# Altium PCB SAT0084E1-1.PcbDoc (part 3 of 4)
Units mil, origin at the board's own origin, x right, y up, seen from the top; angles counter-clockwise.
Board outline 7055 x 5555 mil, 6 copper layers (Top Layer, MidLayer1-GND, MidLayer2-HiSp, MidLayer3-GND, MidLayer4, Bottom Layer), stack 57.4 mil thick; 379 components, 207 nets, 1026 pads, 1546 vias.
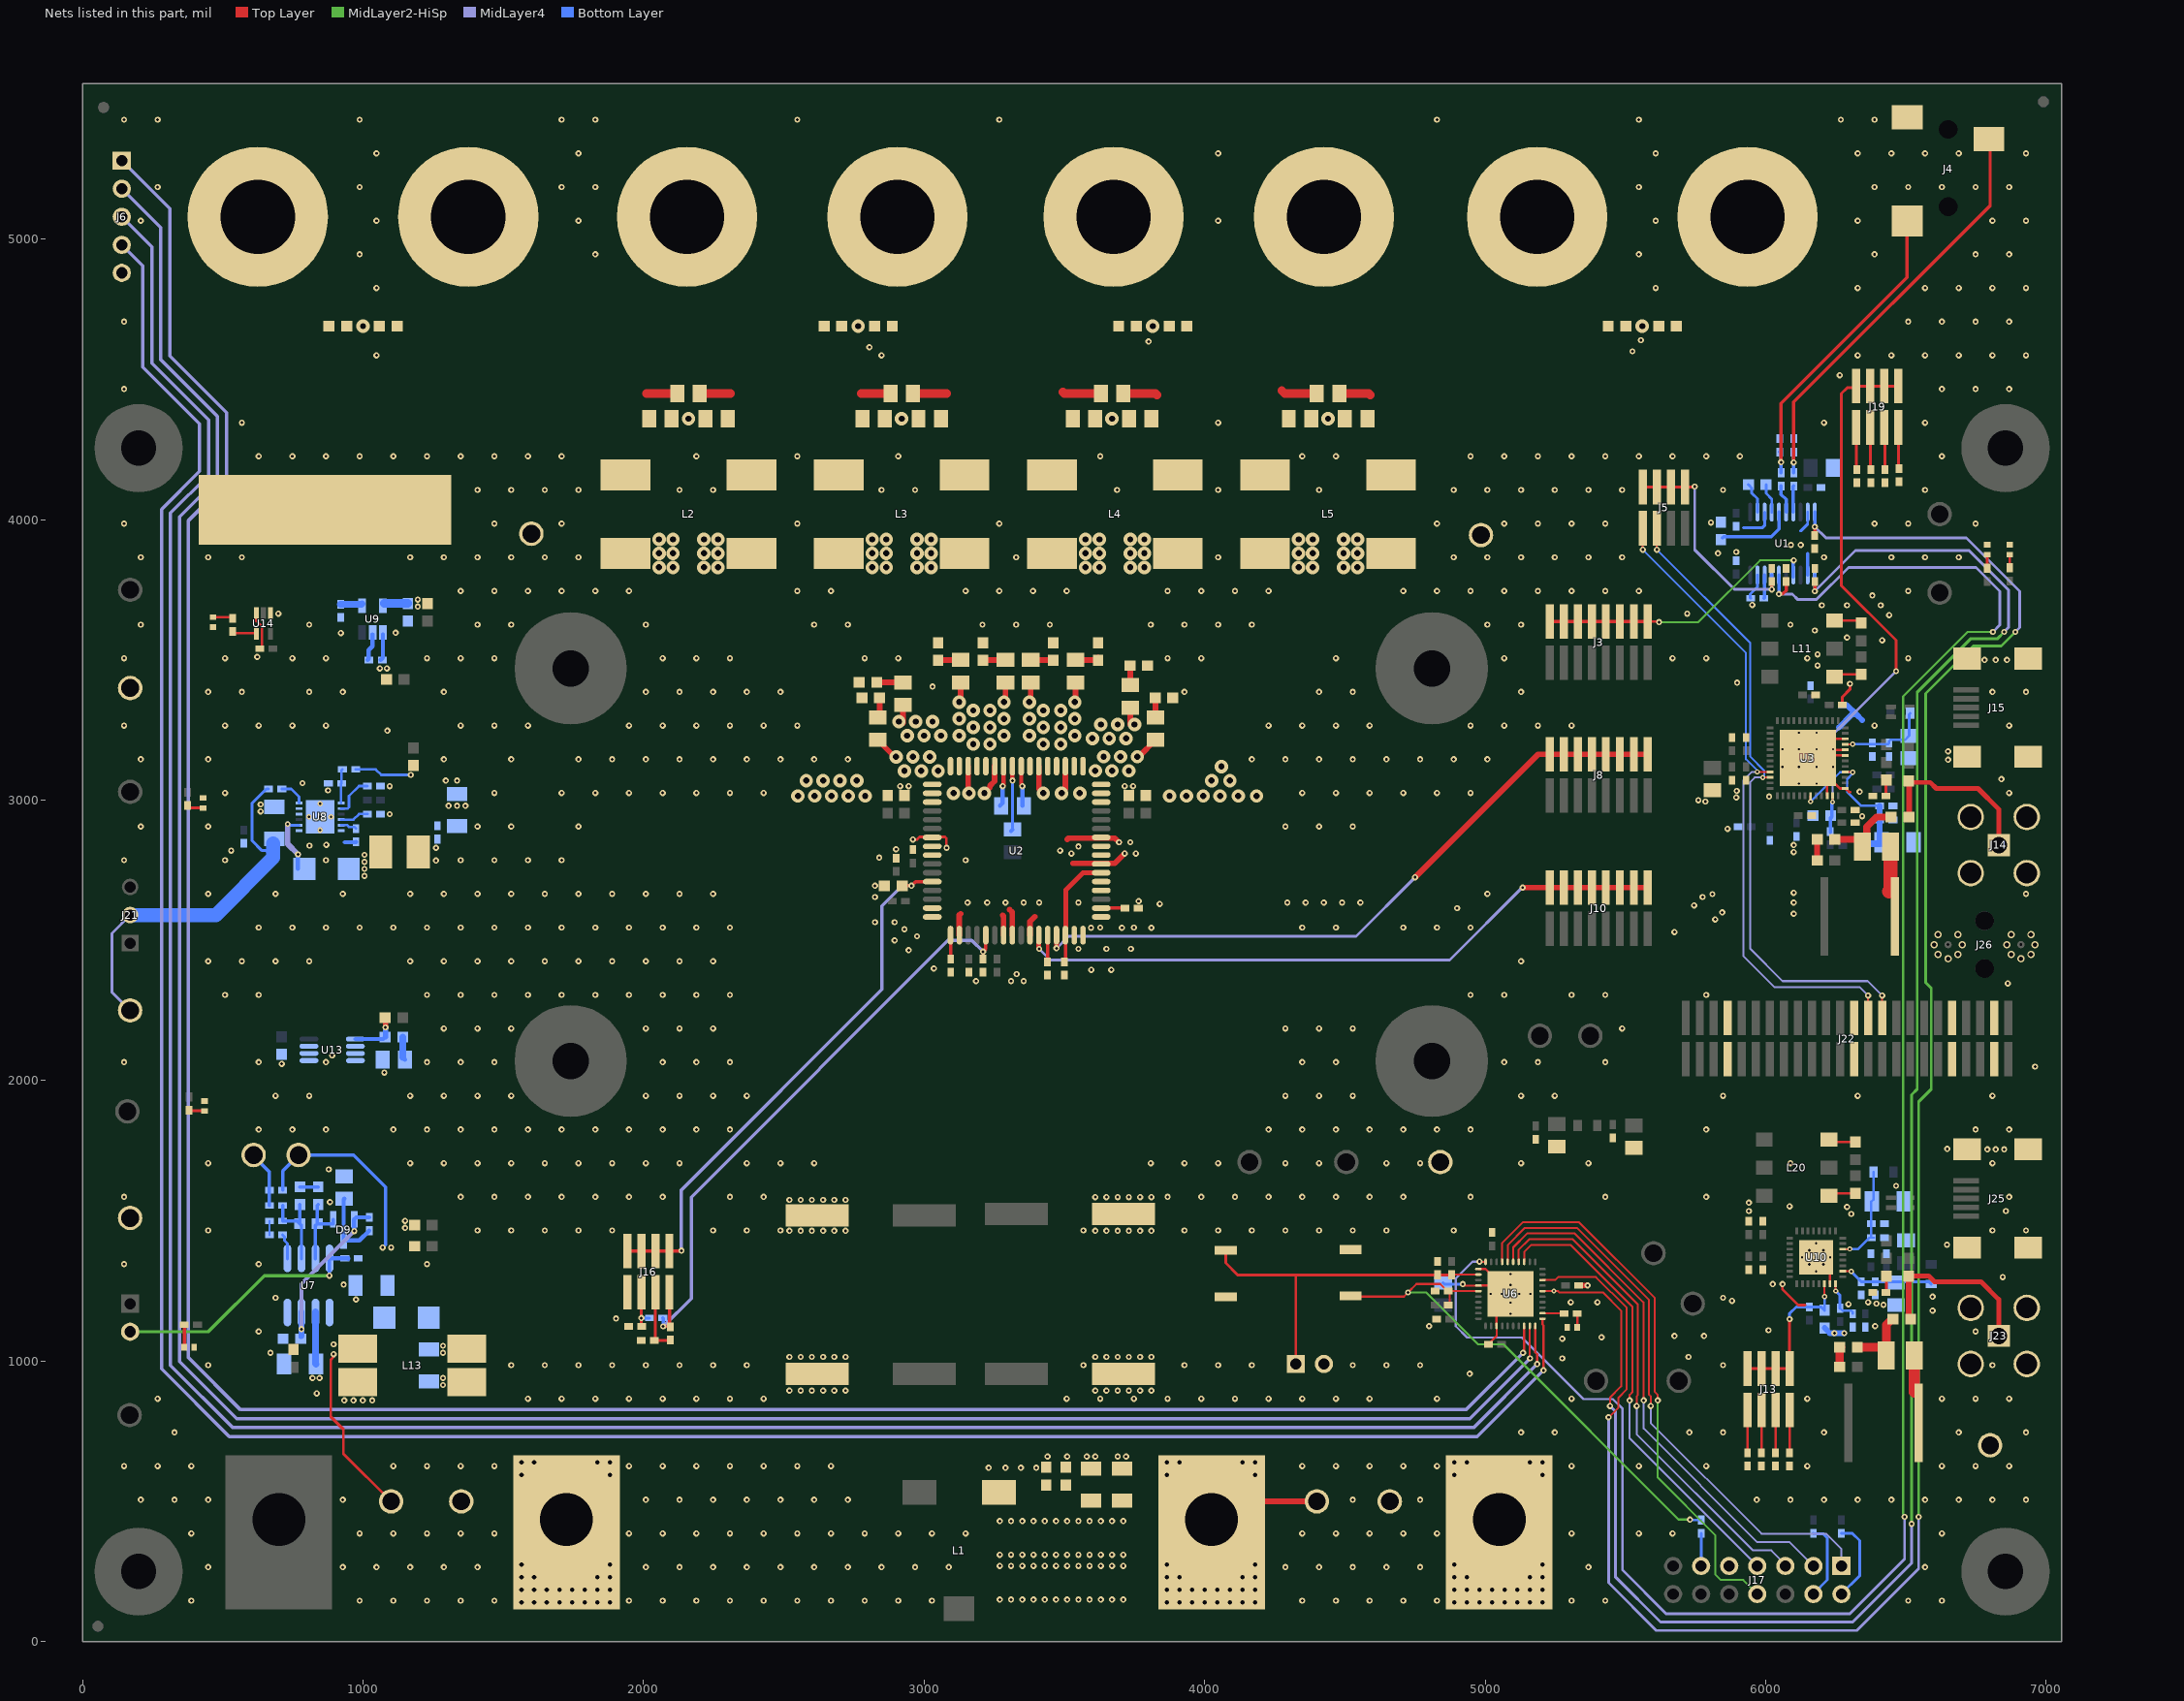
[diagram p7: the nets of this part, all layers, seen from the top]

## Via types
v1: diameter 22, hole 10, Top Layer to Bottom Layer, tented both sides, 1179 vias
v2: diameter 48, hole 22, Top Layer to Bottom Layer, tented both sides, 128 vias
v3: diameter 32, hole 16, Top Layer to Bottom Layer, tented both sides, 112 vias
v4: diameter 18, hole 8, Top Layer to Bottom Layer, tented both sides, 80 vias
v5: diameter 19.68, hole 7.87, Top Layer to Bottom Layer, tented both sides, 30 vias
v6: diameter 26, hole 16, Top Layer to Bottom Layer, 12 vias
v7: diameter 36, hole 16, Top Layer to Bottom Layer, tented both sides, 2 vias
v8: diameter 26, hole 10, Top Layer to Bottom Layer, tented both sides, 1 vias
v9: diameter 20, hole 8, Top Layer to Bottom Layer, tented both sides, 1 vias
v10: diameter 30, hole 12, Top Layer to Bottom Layer, tented both sides, 1 vias

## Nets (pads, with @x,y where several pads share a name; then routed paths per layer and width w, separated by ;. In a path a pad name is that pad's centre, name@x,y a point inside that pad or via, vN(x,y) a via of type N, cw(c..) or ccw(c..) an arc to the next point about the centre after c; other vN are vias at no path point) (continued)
GND: C1.2 C2.2 C3.2 C4.2 C5.2 C6.2 C7.2 C8.2 C9.2 C10.2 C11.2 C12.2 C13.2 C14.2 C15.2 C16.2 C17.2 C18.2 C19.1 C20.2 C21.2 C23.2 C24.2 C25.2 C27.1 C28.2 C29.2 C32.1 C33.1 C34.1 C35.2 C36.1 C37.2 C38.2 C40.1 C41.1 C42.1 C43.1 C44.1 C45.2 C46.2 C48.1 C49.1 C50.1 C51.1 C52.2 C53.2 C55.1 C56.1 C57.1 C58.2 C59.2 C60.2 C61.2 C62.2 C63.2 C64.2 C65.2 C66.2 C67.2 C68.2 C69.2 C70.2 C71.2 C72.2 C73.2 C74.2 C75.2 C76.2 C77.2 C78.2 C87.2 C88.2 C89.2 C91.2 C92.2 C95.2 C96.1 C98.2 C99.2 C100.2 C101.2 C102.2 C103.2 C104.2 C105.2 C106.2 C107.2 C108.2 C109.2 C110.2 C111.2 C112.2 C113.2 C114.2 C115.2 C116.2 C117.2 C118.2 C119.2 C120.2 C127.2 C128.2 C129.2 C130.2 C131.2 C132.2 D1.2 D2.2 D4.2 D6.2 D7.2 D8.2 D10.2 J2.1 J4.1 J6.5 J14.MH1 J14.MH2 J14.MH3 J14.MH4 J15.6 J15.7 J15.8 J15.9 J16.1 J17.9 J20.1 J22.7 J22.8 J22.25 J22.26 J22.39 J22.40 J22.45 J22.46 J23.MH1 J23.MH2 J23.MH3 J23.MH4 J25.6 J25.7 J25.8 J25.9 J26.1A J26.2A J27.2 L13.2 Logo1.0 R1.1 R2.1 R4.1 R5.1 R6.1 R9.2 R10.2 R19.2 R20.2 R25.2 R38.1 R39.1 R40.1 R48.1 R52.1 R53.1 R54.2 R57.1 R63.1 R74.2 R90.1 R91.1 R94.1 R96.1 R98.2 R100.2 R103.1 R104.1 R105.1 R106.1 R107.1 S1.2 S5.1 TP2.1 TP3.1 TP4.1 TP9.1 TP14.1 TP17.1 TP41.1 TP48.1 U1.3 U1.9 U1.12 U1.19 U2.2 U2.7 U2.8 U2.10 U2.15 U2.16 U2.17 U2.20 U2.21 U2.23 U2.24 U2.25 U2.26 U2.30 U2.31 U2.32 U2.35 U2.38 U2.39 U2.43 U2.46 U2.49 U2.50 U2.51 U2.55 U2.56 U2.57 U2.63 U2.64 U3.34 U3.37 U3.43 U3.44 U3.46 U3.49 U6.1 U6.4 U6.13 U6.41 U7.4 U8.4 U8.5 U8.13 U9.2 U10.7 U10.33 U13.2 U13.3 U13.4 U13.5 U13.6 U13.7 U14.1 U14.3 | length 3797.5
  Top Layer w7: v1(4920,1275) 4925.47,1269.53 U6.4@4975.83,1269.53 ; C128.2@5011.38,1060 5040.79,1089.41 U6.13@5040.79,1125.83
  Top Layer w8: U6.4@4975.83,1269.53 U6.41@5060.47,1269.53 ; U6.1@4975.83,1328.58 5001.42,1328.58 U6.41@5060.47,1269.53 ; U6.13@5040.79,1125.83 5040.79,1190.79 U6.41@5090,1240 U6.41@5060.47,1269.53 ; v5(6180,1370) v1(6205,1345) 6229.21,1320.79 U10.7@6229.21,1275.51
  Top Layer w9: U14.3@620,3675 620,3639 640,3619 640,3548.62 C112.2@631.38,3540 ; v1(2960,2860) 2975,2860 2984,2869 3074,2869 3080,2863 v1(3080,2830) ; v1(6060,1275) 6060,1256 6116,1200 6140,1200 ; U3.34@6218.9,3016.14 6218.9,3068.9 6228,3078 6264.27,3041.73 U3.37@6283.86,3041.73 6296.59,3029 6302,3029 ; U3.49@6225,3075 U3.49@6150,3150 U3.49@6159.84,3159.84 ; U3.43@6283.86,3159.84 U3.49@6159.84,3159.84 ; U3.44@6283.86,3179.53 U3.49@6179.53,3179.53 ; U3.46@6283.86,3218.9 6218.9,3218.9 U3.49@6179.53,3179.53 ; U3.49@6159.84,3159.84 U3.49@6179.53,3179.53
  Top Layer w10: C70.2@6273.62,3340 6273.62,3368.62 6300,3395 v1(6300,3415)
  Top Layer w20: U2.2@3125.59,2518.82 3125.59,2590.59 3130,2595 ; U2.46@3157.09,3121.18 3157.09,3027.91 v2(3160,3025) ; v2(3215,3025) 3235,3045 3235,3051 3251.57,3067.57 U2.43@3251.57,3121.18 ; 3280,2590 3283.07,2586.93 U2.7@3283.07,2518.82 ; 3305,2610 3314.57,2600.43 U2.8@3314.57,2518.82 ; U2.10@3377.56,2518.82 3377.56,2567.56 3395,2585 ; U2.38@3409.06,3121.18 3409.06,3040.94 v2(3425,3025) ; v2(3490,3025) 3503.54,3038.54 U2.35@3503.54,3121.18 ; 3510,2860 3515,2865 3680,2865 v1(3695,2850) ; 3530,2775 3680,2775 v1(3715,2810) ; R1.1@5333.62,1270 v1(5365,1270)
  Bottom Layer w8: R53.1@666.38,1450 R52.1@666.38,1500
  Bottom Layer w10: C87.2@4850,1280 4855,1275 v1(4920,1275) ; 5920,3972 5989,3972 5996.02,3979.02 U1.3@5996.02,4027.2 ; C19.1@5946.38,3720 5945,3721.38 5945,3735 5970.43,3760.43 U1.19@5970.43,3802.8 ; 6125,3960 6149.57,3984.57 U1.9@6149.57,4027.2 ; 6149.57,3879.57 6150,3880
  Bottom Layer w12: U1.12@6149.57,3802.8 6149.57,3879.57
  Bottom Layer w15: C101.2@1016.38,3500 1020,3503.62 1020,3535 1033.76,3548.76 U9.2@1033.76,3591.17
  Bottom Layer w20: C111.2@6210,1118.5 6228.5,1100 v1(6245,1100) v1(6280,1100) ; 6261,3259 6307,3305 6324,3305 ; C71.2@6273.62,3340 6289,3340 6324,3305 ; 6344,3285 6324,3305
  other v1: 388,146 988,146 1108,146 1228,146 1348,146 1468,146 1948,146 2068,146 2188,146 2308,146 2428,146 2548,146 2668,146 2788,146 2908,146 3028,146 4348,146 4468,146 4588,146 4708,146 4828,146 5308,146 5428,146 6508,146 6628,146 448,266 928,266 1048,266 1168,266 1288,266 1408,266 2008,266 2128,266 2248,266 2368,266 2488,266 2608,266 2728,266 2848,266 2968,266 3088,266 4288,266 4408,266 4528,266 4648,266 4768,266 5368,266 6568,266 388,386 988,386 1108,386 1228,386 1348,386 1468,386 1948,386 2068,386 2188,386 2308,386 2428,386 2548,386 2668,386 2788,386 2908,386 3028,386 3148,386 4348,386 4468,386 4588,386 4708,386 4828,386 5308,386 5548,386 5668,386 6628,386 208,506 328,506 448,506 928,506 2008,506 2128,506 2248,506 2368,506 2488,506 2608,506 2728,506 4528,506 4768,506 5968,506 6088,506 6208,506 6328,506 6448,506 6568,506 6688,506 6808,506 6928,506 3230,620 3290,620 3345,620 3400,620 148,626 268,626 388,626 1108,626 1228,626 1348,626 1468,626 1948,626 2068,626 2188,626 2308,626 2428,626 2548,626 2668,626 4348,626 4468,626 4588,626 4708,626 4828,626 5308,626 5548,626 5788,626 6148,626 6628,626 6748,626 6868,626 3440,660 3510,660 3580,660 3610,660 3690,660 3720,660 328,746 5128,746 5248,746 5728,746 5848,746 6208,746 6688,746 6928,746 933,860 966,860 999,860 1033,860 268,866 1588,866 1708,866 1828,866 1948,866 2068,866 2188,866 2308,866 2428,866 3508,866 3628,866 3748,866 3868,866 3988,866 4108,866 4228,866 4348,866 4468,866 4588,866 4828,866 5308,866 6148,866 6628,866 6748,866 6868,866 835,885 2520,895 2560,895 2600,895 2640,895 2680,895 2720,895 3610,895 3650,895 3690,895 3730,895 3770,895 3810,895 4945,955 448,986 1528,986 1648,986 1768,986 1888,986 2008,986 2128,986 2248,986 2368,986 3568,986 3928,986 4048,986 4168,986 4528,986 4648,986 4768,986 5848,986 6808,986 5275,1010 2520,1015 2560,1015 2600,1015 2640,1015 2680,1015 2720,1015 3610,1015 3650,1015 3690,1015 3730,1015 3770,1015 3810,1015 5725,1015 670,1030 5275,1080 5415,1085 5675,1090 5780,1090 628,1106 6748,1106 6010,1110 4800,1125 6390,1125 1902,1152 6595,1180 6420,1201 6295,1203 6395,1205 5305,1210 5400,1210 6365,1210 5880,1215 975,1220 688,1226 5848,1226 6595,1230 931,1273 6025,1275 6845,1300 6155,1345 148,1346 628,1346 1228,1346 6155,1395 6205,1395 6646,1415 2520,1465 2560,1465 2600,1465 2640,1465 2680,1465 2720,1465 3610,1465 3650,1465 3690,1465 3730,1465 3770,1465 3810,1465 448,1466 1408,1466 1528,1466 1648,1466 1768,1466 1888,1466 2248,1466 2368,1466 2488,1466 3568,1466 3928,1466 4048,1466 4168,1466 4288,1466 4408,1466 4528,1466 4648,1466 4888,1466 6808,1466 6928,1466 1150,1475 1150,1500 6305,1525 5940,1535 6856,1535 6290,1550 6085,1552 5940,1565 882,1567 2520,1575 2560,1575 2600,1575 2640,1575 2680,1575 2720,1575 3610,1585 3650,1585 3690,1585 3730,1585 3770,1585 3810,1585 148,1586 1348,1586 1468,1586 1588,1586 1708,1586 1828,1586 1948,1586 2068,1586 2308,1586 2428,1586 3868,1586 3988,1586 4108,1586 4228,1586 4348,1586 4468,1586 4588,1586 4708,1586 4948,1586 5428,1586 5788,1586 6868,1586 6465,1625 878,1684 448,1706 1168,1706 1288,1706 1408,1706 1528,1706 1648,1706 1768,1706 1888,1706 2008,1706 2128,1706 2368,1706 2488,1706 2608,1706 3808,1706 3928,1706 4048,1706 4288,1706 4408,1706 4648,1706 4768,1706 5128,1706 5368,1706 6088,1706 6808,1706 6790,1755 6820,1755 6850,1755 6647,1757 628,1826 748,1826 868,1826 1108,1826 1228,1826 1348,1826 1468,1826 1588,1826 1708,1826 1828,1826 1948,1826 2068,1826 2188,1826 2308,1826 4228,1826 4348,1826 4468,1826 4588,1826 4708,1826 4828,1826 4948,1826 5788,1826 6748,1826 6868,1826 688,1946 808,1946 1168,1946 1288,1946 1408,1946 1528,1946 2008,1946 2128,1946 2248,1946 2368,1946 4288,1946 4408,1946 4528,1946 5128,1946 5248,1946 5848,1946 6328,1946 6808,1946 1076,2029 6960,2050 710,2060 148,2066 628,2066 868,2066 1228,2066 1348,2066 1468,2066 2068,2066 2188,2066 2308,2066 4348,2066 4468,2066 5068,2066 5188,2066 5428,2066 890,2090 1288,2186 1408,2186 1528,2186 2008,2186 2128,2186 2248,2186 4288,2186 4408,2186 4528,2186 5488,2186 508,2306 628,2306 1228,2306 1348,2306 1468,2306 1588,2306 1708,2306 1828,2306 1948,2306 2068,2306 2188,2306 2308,2306 4948,2306 5068,2306 5308,2306 5428,2306 5788,2306 6863,2347 3185,2355 3310,2355 3355,2355 3330,2380 3596,2395 3667,2395 3035,2400 448,2426 568,2426 688,2426 808,2426 1168,2426 1288,2426 1408,2426 1528,2426 1648,2426 1768,2426 1888,2426 2008,2426 2128,2426 2248,2426 5128,2426 2945,2465 3550,2470 3650,2470 3737,2470 2895,2500 2975,2515 5675,2530 2930,2540 3595,2545 3705,2545 3810,2545 628,2546 748,2546 868,2546 988,2546 1108,2546 1228,2546 1348,2546 1468,2546 1588,2546 1708,2546 1828,2546 1948,2546 2068,2546 2188,2546 2308,2546 3628,2546 3748,2546 4348,2546 4468,2546 4708,2546 4828,2546 4948,2546 2825,2565 2895,2565 5820,2575 6100,2595 5845,2600 4900,2615 5745,2625 3840,2630 3155,2635 3225,2635 3290,2635 3355,2635 3410,2635 3550,2635 4295,2635 4360,2635 4425,2635 4490,2635 4555,2635 6100,2635 3765,2640 2825,2655 5775,2655 5810,2665 448,2666 688,2666 928,2666 1168,2666 1288,2666 1408,2666 1528,2666 1648,2666 1768,2666 1888,2666 2008,2666 2128,2666 2248,2666 5008,2666 6928,2666 6100,2670 2825,2695 148,2786 508,2786 868,2786 1348,2786 1468,2786 1588,2786 1708,2786 3148,2786 2840,2795 3525,2810 3755,2810 6100,2815 530,2820 3485,2820 2900,2825 3550,2835 809,2838 6100,2840 869,2841 3735,2850 5864,2898 208,2906 448,2906 1408,2906 1528,2906 1768,2906 4288,2906 4408,2906 4528,2906 6344,2943 1095,2950 635,2960 1305,2980 1335,2980 1365,2980 635,2985 5785,2995 5760,3000 5895,3010 6012,3013 508,3026 1468,3026 1708,3026 1828,3026 1948,3026 2068,3026 2188,3026 2308,3026 2428,3026 4348,3026 4468,3026 4588,3026 4708,3026 4828,3026 4948,3026 6868,3026 6335,3030 5897,3033 875,3035 1095,3050 2915,3050 2945,3050 3715,3050 3745,3050 784,3061 1295,3070 1335,3070 6840,3075 6650,3144 208,3146 448,3146 1288,3146 1528,3146 1768,3146 1888,3146 2008,3146 2128,3146 2248,3146 2368,3146 2488,3146 2608,3146 2728,3146 4168,3146 4288,3146 4408,3146 4528,3146 4648,3146 4768,3146 4888,3146 5008,3146 6650,3174 1087,3248 148,3266 508,3266 628,3266 748,3266 868,3266 1348,3266 1468,3266 1588,3266 1948,3266 2068,3266 2188,3266 2308,3266 2428,3266 2548,3266 4228,3266 4348,3266 4468,3266 4588,3266 4948,3266 5068,3266 5188,3266 5308,3266 6388,3266 6868,3266 448,3386 568,3386 808,3386 928,3386 1288,3386 2008,3386 2128,3386 2248,3386 2368,3386 2488,3386 3928,3386 4408,3386 4528,3386 5128,3386 6808,3386 6928,3386 3030,3405 5898,3419 6185,3480 6780,3500 6820,3500 6860,3500 148,3506 508,3506 748,3506 868,3506 1228,3506 1348,3506 1468,3506 2068,3506 2188,3506 2308,3506 2788,3506 2908,3506 3868,3506 3988,3506 4468,3506 5068,3506 5668,3506 5788,3506 6148,3506 6508,3506 623,3511 6185,3520 6415,3570 6290,3580 921,3596 1116,3597 6175,3605 208,3626 808,3626 1408,3626 1528,3626 2008,3626 2608,3626 2728,3626 3208,3626 3328,3626 3448,3626 3808,3626 3928,3626 4048,3626 4168,3626 5008,3626 5128,3626 6088,3626 6440,3660 698,3665 5720,3665 6200,3695 6290,3695 6410,3695 5952,3696 6380,3730 1348,3746 1468,3746 1588,3746 1708,3746 1828,3746 1948,3746 2548,3746 2668,3746 3148,3746 3268,3746 3388,3746 3508,3746 3868,3746 3988,3746 4108,3746 4228,3746 4708,3746 4828,3746 4948,3746 5068,3746 5188,3746 5308,3746 5428,3746 5548,3746 6508,3746 208,3866 448,3866 568,3866 1168,3866 1288,3866 1408,3866 1528,3866 1648,3866 1768,3866 3328,3866 4048,3866 4888,3866 5008,3866 5128,3866 5248,3866 5368,3866 5488,3866 6208,3866 6448,3866 6568,3866 6688,3866 5830,3880 5895,3885 6090,3910 6125,3910 148,3986 1468,3986 1708,3986 2548,3986 3268,3986 4828,3986 5068,3986 5188,3986 5308,3986 5428,3986 6388,3986 6508,3986 6748,3986 5805,3990 1408,4106 1528,4106 1648,4106 1768,4106 2128,4106 2248,4106 2848,4106 2968,4106 3688,4106 4048,4106 4408,4106 4888,4106 5008,4106 5128,4106 5248,4106 5368,4106 5488,4106 5848,4106 6568,4106 628,4226 748,4226 868,4226 988,4226 1108,4226 1228,4226 1348,4226 1468,4226 1588,4226 1708,4226 2188,4226 2548,4226 2908,4226 3628,4226 4348,4226 4468,4226 4948,4226 5068,4226 5188,4226 5308,4226 5428,4226 5548,4226 5668,4226 5788,4226 5908,4226 6628,4226 568,4346 4048,4346 6208,4346 6568,4346 148,4466 6628,4466 6748,4466 6868,4466 6264,4515 1048,4586 2848,4586 6328,4586 6448,4586 6568,4586 6688,4586 6808,4586 6928,4586 5525,4600 2805,4615 3800,4635 5555,4640 148,4706 6508,4706 6628,4706 6748,4706 6868,4706 1048,4826 5608,4826 6328,4826 6568,4826 6688,4826 6808,4826 6928,4826 988,4946 1828,4946 5548,4946 6388,4946 6748,4946 6868,4946 208,5066 1048,5066 1768,5066 4048,5066 5608,5066 6328,5066 6808,5066 6928,5066 268,5186 988,5186 1708,5186 1828,5186 5548,5186 6388,5186 6508,5186 6628,5186 6748,5186 6868,5186 1048,5306 1768,5306 4048,5306 5608,5306 6328,5306 6448,5306 6568,5306 6688,5306 6928,5306 148,5426 268,5426 988,5426 1708,5426 1828,5426 2548,5426 3268,5426 4828,5426 5548,5426 6268,5426 6388,5426
  other v2: 2550,3015 2610,3015 2670,3015 2730,3015 2790,3015 3875,3015 3935,3015 3995,3015 4055,3015 4120,3015 4185,3015 3105,3025 3555,3025 2580,3070 2640,3070 2700,3070 2760,3070 4025,3070 4090,3070 4060,3120 2160,4360 2920,4360 3670,4360 4440,4360 1000,4690 2765,4690 3815,4690 5560,4690
  other v3: 1565,140 1610,140 1655,140 1700,140 1745,140 1790,140 1835,140 1880,140 4890,140 4935,140 4980,140 5025,140 5070,140 5115,140 5160,140 5205,140 1565,185 1610,185 1655,185 1700,185 1745,185 1790,185 1835,185 1880,185 4890,185 4935,185 4980,185 5025,185 5070,185 5115,185 5160,185 5205,185 1565,230 1610,230 1835,230 1880,230 4890,230 4935,230 5160,230 5205,230 1565,275 1880,275 4890,275 5205,275 1565,595 1880,595 4890,595 5205,595 1565,640 1610,640 1835,640 1880,640 4890,640 4935,640 5160,640 5205,640
  other v5: 5090,1169.13 5090,1208.5 5019.13,1240 5058.5,1240 5121.5,1240 5160.87,1240 5090,1271.5 5090,1310.87 6180,1320 6130,1370 6230,1370 6180,1420 846.9,2893.31 807.53,2940.56 846.9,2940.56 886.28,2940.56 846.9,2987.8 6118.54,3059.42 6181.46,3059.42 6059.42,3118.54 6118.54,3118.54 6181.46,3118.54 6240.58,3118.54 6059.42,3181.46 6118.54,3181.46 6181.46,3181.46 6240.58,3181.46 6118.54,3240.58 6181.46,3240.58
  other v6: 6614.72,2449.68 6685.43,2449.68 6874.57,2449.68 6945.28,2449.68 6600.08,2485.04 6700.08,2485.04 6859.92,2485.04 6959.92,2485.04 6614.72,2520.39 6685.43,2520.39 6874.57,2520.39 6945.28,2520.39
JTAG_TCK: J17.7 U6.33 | length 1640.9
  Top Layer w7: U6.33@5139.21,1354.17 5139.21,1389.21 5165,1415 5303.64,1415 5525,1193.64 5525,890 5515,880 v1(5515,860) v1@5515,855
  MidLayer4 w7: v1(5515,860) 5515,725 5955,285 J17.7@5967.5,297.5
JTAG_TDI: J17.3 U6.35 | length 1890.8
  Top Layer w7: U6.35@5099.84,1354.17 5099.84,1405.52 5149.32,1455 5319.32,1455 5564.37,1209.95 v1@5564.37,865
  MidLayer4 w7: v1(5565,860) 5565,760 5970,355 6085,355 J17.3@6170,270
JTAG_TDO: J17.1 U6.36 | length 2067.2
  Top Layer w7: U6.36@5080.16,1354.17 5080.16,1413.67 5141.48,1475 5327.16,1475 5584.06,1218.11 5584.06,880.94 5590,875 v1(5590,840)
  MidLayer4 w7: v1(5590,840) 5590,780 5985,385 6215,385 6270,330 J17.1@6270,265
JTAG_TMS: J17.5 U6.34 | length 1774
  Top Layer w7: U6.34@5119.53,1354.17 5119.53,1397.37 5157.16,1435 5311.48,1435 5544.69,1201.8 5544.69,879.69 5540,875 v1(5540,840)
  MidLayer4 w7: v1(5540,840) 5540,740 5955,325 6020,325 J17.5@6075,270
NetC10_1: C10.1 C11.1 C12.1 C13.1 J1.1 L1.1 TP1.1 | length 401.9
  Top Layer w20: J1.1@4025,435 4090,500 TP1.1@4400,500
  other v1: 3270,150 3310,150 3350,150 3390,150 3430,150 3470,150 3510,150 3550,150 3590,150 3630,150 3670,150 3710,150 3270,270 3310,270 3350,270 3390,270 3430,270 3470,270 3510,270 3550,270 3590,270 3630,270 3670,270 3710,270 3270,310 3310,310 3350,310 3390,310 3430,310 3470,310 3510,310 3550,310 3590,310 3630,310 3670,310 3710,310 3270,430 3310,430 3350,430 3390,430 3430,430 3470,430 3510,430 3550,430 3590,430 3630,430 3670,430 3710,430
  other v3: 3865,140 3910,140 3955,140 4000,140 4045,140 4090,140 4135,140 4180,140 3865,185 3910,185 3955,185 4000,185 4045,185 4090,185 4135,185 4180,185 3865,230 3910,230 4135,230 4180,230 3865,275 4180,275 3865,595 4180,595 3865,640 3910,640 4135,640 4180,640
NetC19_2: C19.2 U1.18 | length 83.8
  Bottom Layer w12: C19.2@5993.62,3720 5996.02,3722.4 U1.18@5996.02,3802.8
NetC20_1: C20.1 J4.2 R7.2 | length 1129.3
  Top Layer w12: v1(6055,4205) 6055,4415 6504.33,4864.33 J4.2@6504.33,5064.96
  Top Layer w15: J4.2@6504.33,5064.96 J4.2@6509.29,5060
  Bottom Layer w12: C20.1@6050,4241.38 6055,4236.38 v1(6055,4205) R7.2@6055,4167.24
NetC21_1: C21.1 J4.3 R8.2 | length 1517.9
  Top Layer w12: v1(6100,4204.31) 6100,4420 6800,5120 J4.3@6800,5351.97
  Top Layer w15: J4.3@6795.67,5356.3 J4.3@6800,5351.97
  Bottom Layer w12: R8.2@6100,4167.24 v1(6100,4204.31) C21.1@6100,4241.38
NetC22_1: C22.1 U1.2 | length 111
  Bottom Layer w10: C22.1@5938.5,4125 5950,4113.5 5950,4095 5970.43,4074.57 U1.2@5970.43,4027.2
NetC22_2: C22.2 U1.4 | length 106.1
  Bottom Layer w10: C22.2@6001.5,4125 6001.5,4093.5 6021.61,4073.39 U1.4@6021.61,4027.2
NetC23_1: C23.1 U1.5 | length 275.5
  Bottom Layer w12: C23.1@5845,3935 5850,3940 6020,3940 6047.2,3967.2 U1.5@6047.2,4027.2
NetC24_1: C24.1 J16.7 R97.1 R99.1 U2.5 | length 2205.7
  Top Layer w12: v1(2070,1124) R99.1@2093.62,1124 ; J16.7@2092,1245.48 2092,1125.62 R99.1@2093.62,1124 ; R99.1@2095,1122.62 R99.1@2093.62,1124 ; C24.1@3210,2433.62 v1(3210,2460) 3220.08,2470.08 U2.5@3220.08,2518.82
  MidLayer4 w12: v1(2070,1124) 2170,1224 2170,1585 3085,2500 3170,2500 v1(3210,2460)
  Bottom Layer w12: R97.1@2068.62,1154 2070,1152.62 v1(2070,1124)
NetC25_1: C25.1 U2.14 U2.22 | length 410.3
  Top Layer w12: C25.1@3500,2423.62 3503.54,2427.17 U2.14@3503.54,2518.82
  Top Layer w17: U2.14@3503.54,2518.82 3505,2520.28 3505,2680 3566.26,2741.26 U2.22@3631.5,2741.26
NetC26_1: C26.1 U2.42 | length 146.6
  Top Layer w15: v1(3280,3050) 3283.07,3053.07 U2.42@3283.07,3121.18
  Bottom Layer w15: C26.1@3270,2980 3280,2990 v1(3280,3050)
NetC26_2: C26.2 U2.40 | length 142.8
  Top Layer w15: U2.40@3346.06,3121.18 3346.06,3053.94 v1(3350,3050)
  Bottom Layer w15: C26.2@3350,2980 v1(3350,3050)
NetC27_2: C27.2 R11.2 | length 78.5
  Top Layer w20: C27.2@2831.5,3420 R11.2@2910,3420
NetC28_1: C28.1 C29.1 C31.1 J7.1 L2.2 | length 110
  Top Layer w30: C31.1@2200,4450 2310,4450
NetC30_2: C30.2 U2.41 | length 233.4
  Top Layer w15: U2.41@3314.57,3121.18 3314.57,3070.43 v1(3315,3070)
  Bottom Layer w10: C30.2@3315,2895 v1(3315,3070)
  Bottom Layer w15: C30.2@3310,2890 C30.2@3315,2895
NetC31_2: C31.2 C33.2 C34.2 J7.2 L2.3 | length 110
  Top Layer w30: 2010,4450 C31.2@2120,4450
NetC32_2: C32.2 R12.2 | length 68.5
  Top Layer w20: R12.2@2841.5,3296.5 C32.2@2841.5,3365
NetC35_1: C35.1 U2.1 | length 91.1
  Top Layer w12: C35.1@3094.09,2427.72 U2.1@3094.09,2518.82
NetC36_2: C36.2 R13.2 | length 75.6
  Top Layer w20: C36.2@3218.5,3500 3280,3500 R13.2@3290,3510
NetC37_1: C37.1 C38.1 C39.1 J9.1 L3.2 | length 120
  Top Layer w30: C39.1@2960,4450 3080,4450
NetC39_2: C39.2 C41.2 C42.2 J9.2 L3.3 | length 105
  Top Layer w30: 2775,4450 C39.2@2880,4450
NetC40_2: C40.2 R14.2 | length 80.6
  Top Layer w20: C40.2@3050,3498.5 3051.5,3500 R14.2@3130,3500
NetC43_2: C43.2 U2.18 | length 96.8
  Top Layer w12: U2.18@3631.5,2615.28 3721.65,2615.28 C43.2@3726.38,2620
NetC44_2: C44.2 R15.2 | length 83.5
  Top Layer w20: R15.2@3540,3500 3611.5,3500 C44.2@3620,3508.5
NetC45_1: C45.1 C46.1 C47.1 J11.1 L4.2 | length 122.1
  Top Layer w30: C47.1@3710,4450 3825,4450 3830,4445
NetC47_2: C47.2 C49.2 C50.2 J11.2 L4.3 | length 137.1
  Top Layer w30: 3495,4455 3500,4450 C47.2@3630,4450
NetC48_2: C48.2 R16.2 | length 78.5
  Top Layer w20: R16.2@3380,3500 C48.2@3458.5,3500
NetC51_2: C51.2 R17.2 | length 68.5
  Top Layer w20: R17.2@3825,3296.5 C51.2@3825,3365
NetC52_1: C52.1 C53.1 C54.1 J12.1 L5.2 | length 112.1
  Top Layer w30: C54.1@4480,4450 4585,4450 4590,4445
NetC54_2: C54.2 C56.2 C57.2 J12.2 L5.3 | length 129.1
  Top Layer w30: 4275,4460 4285,4450 C54.2@4400,4450
NetC55_2: C55.2 R18.2 | length 78.5
  Top Layer w20: R18.2@3735,3405 C55.2@3735,3483.5
NetC73_1: C73.1 C74.1 C75.1 L7.2 U3.45 | length 325.6
  Top Layer w8: U3.45@6283.86,3199.21 6309.21,3199.21 v4(6310,3200)
  Bottom Layer w8: C74.1@6440,3203.62 6440,3210 6445,3215 6496.46,3215 C75.1@6511.46,3230
  Bottom Layer w9: v4(6310,3200) 6436.38,3200 C74.1@6440,3203.62
  Bottom Layer w10: C75.1@6511.46,3230 6511.46,3306.46 L7.2@6515,3310
NetC76_1: C76.1 C77.1 C78.1 L8.2 U3.31 U3.40 | length 662.2
  Top Layer w7: U3.31@6159.84,3016.14 6159.84,2995.16 v4(6160,2995)
  Top Layer w8: U3.40@6283.86,3100.79 6309.21,3100.79 v4(6310,3100)
  Bottom Layer w8: v4(6160,2995) 6265,3100 v4(6310,3100) 6310,3095 6290,3075 6290,3030 6340,2980 C76.1@6406.38,2980
  Bottom Layer w20: C76.1@6406.38,2980 C77.1@6406.38,2930 6406.38,2846.54 C78.1@6407.91,2845
  Bottom Layer w25: L8.2@6345,2845 6407.91,2845 C78.1@6412.91,2850
NetC82_2: C82.2 J14.1 R31.1 | length 605.5
  Top Layer w17: C82.2@6511.5,3063.5 6586.5,3063.5 6608,3042 6757,3042 6830.87,2968.13 J14.1@6830.87,2840
  Top Layer w20: R31.1@6511.5,2945 C82.2@6511.5,3063.5
NetC86_2: C86.2 R40.2 | length 55.1
  Top Layer w10: R40.2@6428.62,3015 C86.2@6428.62,3070.13
NetC89_1: C89.1 R28.1 R41.1 S5.2 U6.5 | length 1911.9
  Top Layer w7: C89.1@4873.78,1249.84 U6.5@4975.83,1249.84
  Top Layer w8: S5.2@4520,1232.32 4522.32,1230 4710,1230 v1(4725,1245) 4755,1275 4840,1275 4873.62,1241.38 R41.1@4873.62,1200 ; C89.1@4873.62,1250 C89.1@4873.78,1249.84
  MidLayer2-HiSp w8: v1(4725,1245) 4790,1245 4975,1060 5065,1060 5690,435 v1(5730,435)
  Bottom Layer w7: v1(5730,435) v1@5731.38,433.62
  Bottom Layer w8: v1@5731.38,433.62 R28.1@5770,433.62
NetC90_1: C90.1 D3.2 L13.4
  other v1: 1285,1030 1285,1055
NetC90_2: C90.2 L13.3 U7.1
  other v1: 1285,915 1285,940
NetC91_1: C91.1 D3.1 R47.2 R108.1 TP12.1 | length 711.6
  Bottom Layer w12: R47.2@713.62,1610 713.62,1678.62 TP12.1@770,1735 966,1735 1080,1621 1080,1415
  other v1: 1070,1405 1100,1405
NetC92_1: C92.1 L13.1 R44.2 TP10.1 U7.2 | length 804.3
  Top Layer w10: v1(895,1025) 895,1015 885,1005 885,802 930,757 930,670 TP10.1@1100,500
  Bottom Layer w24: U7.2@830.59,1175.51 830.59,991.5 C92.1@832.09,990
  other v1: 820,940 845,940 895,1060
NetC93_1: C93.1 R50.2 R51.1 R52.2 U7.6 | length 316.7
  Bottom Layer w12: R51.1@713.62,1555 R52.2@713.62,1500 764.09,1500 C93.1@774.09,1490 ; R50.2@775,1558.5 774.09,1557.6 C93.1@774.09,1490 ; U7.6@780.59,1364.49 780.59,1483.5 C93.1@774.09,1490
NetC93_2: C93.2 C94.2 D9.1 U7.7 | length 269.8
  Bottom Layer w12: U7.7@830.59,1364.49 U7.7@830.59,1366.46 830.59,1483.5 C93.2@837.09,1490 ; C94.2@840,1558.5 837.09,1555.59 C93.2@837.09,1490 ; D9.1@893.6,1505.4 893.6,1490 C93.2@837.09,1490
NetC94_1: C94.1 R50.1 | length 65
  Bottom Layer w12: R50.1@775,1621.5 C94.1@840,1621.5
NetC95_1: C95.1 D9.2 R32.2 U7.3 | length 618.5
  MidLayer4 w15: v1(780.59,1114) 780.59,1275.59 v1(969,1464)
  Bottom Layer w12: C95.1@776.5,1085 C95.1@780.59,1089.09
  Bottom Layer w15: v1(969,1464) 968.4,1464.6 D9.2@968.4,1505.4 975.62,1512.62 R32.2@1022,1512.62
  Bottom Layer w20: C95.1@780.59,1089.09 v1(780.59,1114) U7.3@780.59,1173.54 U7.3@780.59,1175.51
NetC96_2: C96.2 U8.10 | length 102.1
  Bottom Layer w9: U8.10@921.71,2930.71 965.71,2930.71 985.56,2950.56 C96.2@1015.57,2950.56
NetC97_1: C97.1 U8.11 | length 58.4
  Bottom Layer w9: U8.11@921.71,2911.03 943.97,2911.03 950,2905 968.62,2905 C97.1@975,2898.62
NetC97_2: C97.2 D5.1 L14.1 U8.12 | length 40.6
  Bottom Layer w15: 935,2850 973.62,2850 C97.2@975,2851.38
  other v1: 1005,2730 1005,2755 1005,2780 1005,2805
NetC98_1: C98.1 J21.2 R56.2 TP15.1 U8.1 | length 1352.7
  MidLayer4 w10: TP15.1@169.87,2250.5 105,2315.37 105,2525.64 J21.2@169.87,2590.5
  Bottom Layer w10: R56.2@663.28,3040.56 655.56,3040.56 605,2990 605,2855 640,2820 655,2820 680,2795
  Bottom Layer w50: J21.2@169.87,2590.5 475.5,2590.5 680,2795 C98.1@680,2845
NetC99_1: C99.1 U8.8 | length 150.6
  Bottom Layer w9: U8.8@921.71,2970.08 945.08,2970.08 950,2975 950,3015 985.56,3050.56 C99.1@1015.57,3050.56
NetC100_1: C100.1 R61.1
NetC101_1: C101.1 R64.2 U9.1 | length 94.1
  Bottom Layer w15: C101.1@1063.62,3500 1070.76,3507.14 U9.1@1070.76,3591.17
  other v1: 1060,3470 1085,3470
NetC102_1: C102.1 R65.1 U9.5 | length 85
  Bottom Layer w30: U9.5@1075,3701.5 C102.1@1160,3701.5
  other v1: 1195,3690 1195,3715
NetC103_1: C103.1 U9.4 | length 77.4
  Bottom Layer w25: C103.1@920,3698.62 995.22,3698.62 U9.4@996.76,3700.17
NetC109_1: C109.1 J16.2 J16.4 J16.6 J16.8 U2.60 | length 1956.6
  Top Layer w12: J16.2@1942,1392.52 J16.4@1992,1392.52 J16.6@2042,1392.52 J16.8@2092,1392.52 2133.52,1392.52 v1(2135,1394) ; C109.1@2931.5,2695 v1(2955,2695) 2969.76,2709.76 U2.60@3029.13,2709.76
  MidLayer4 w12: v1(2135,1394) 2135,1494 ; 2135,1495 2135,1610 2850,2325 2850,2623.5 2921.5,2695 v1(2955,2695)
NetC110_1: C110.1 J19.2 J19.4 J19.6 J19.8 R36.1 U3.35 | length 1994.2
  Top Layer w8: v4(6238.25,2993.25) 6238.58,2993.58 U3.35@6238.58,3016.14
  Top Layer w10: J19.2@6320,4470 6290,4470 6270,4450 6270,3765 6465,3570 v1(6465,3460) ; J19.2@6323,4476.02 J19.4@6373,4476.02 J19.6@6423,4476.02 J19.8@6473,4476.02 J19.8@6475,4476.02
  MidLayer4 w8: v4(6238.25,2993.25) 6238.25,3058.25 6218,3078.5 6218,3213 v1(6465,3460)
  Bottom Layer w12: R36.1@6230,2885 C110.1@6230,2937.13 ; C110.1@6233.62,2937.13 6236.5,2940 6236.5,2991.5 v4(6238.25,2993.25) v4@6240,2995
NetC111_1: C111.1 J13.2 J13.4 J13.6 J13.8 R89.1 U10.6 | length 580.5
  Top Layer w7: U10.6@6209.53,1275.51 6209.53,1230.47 v4(6210,1230)
  Top Layer w10: J13.2@5935,973.52 J13.4@5985,973.52 J13.6@6035,973.52 J13.8@6085,973.52 v1(6085,1150)
  Bottom Layer w10: v1(6085,1150) 6085,1170 6108.62,1193.62 R89.1@6155,1193.62 6197.87,1193.62 C111.1@6210,1181.5 v4(6210,1230)
NetC115_1: C115.1 C116.1 C117.1 L16.2 U10.10 | length 330.9
  Top Layer w7: U10.10@6274.49,1320.79 6299.21,1320.79 v4@6300,1320
  Bottom Layer w10: v4@6303.62,1320 C115.1@6340,1283.62 C116.1@6390,1283.62 6581.38,1283.62 L16.2@6590,1275
  other v4: 6305,1320
NetC118_1: C118.1 C119.1 C120.1 L17.2 U10.14 | length 367.2
  Top Layer w7: U10.14@6274.49,1399.53 6299.53,1399.53 v4(6300,1400)
  Bottom Layer w8: v4(6300,1400) 6330,1400 6370,1440 C118.1@6376.38,1440 ; L17.2@6385,1675 6385,1577.09 C120.1@6377.91,1570 6376.38,1568.46 C119.1@6376.38,1490 C118.1@6376.38,1440 ; C118.1@6386.38,1440 C118.1@6376.38,1440
NetC122_2: C122.2 J23.1 R88.1 | length 622
  Top Layer w10: 6511.5,1281.5 C122.2@6515,1285
  Top Layer w17: C122.2@6510,1303.5 6581.5,1303.5 6602,1283 6768,1283 6830.87,1220.13 J23.1@6830.87,1090
  Top Layer w20: R88.1@6510,1160 C122.2@6510,1291.5
NetC126_2: C126.2 R96.2 | length 59.1
  Top Layer w10: R96.2@6428.62,1245 6430,1246.38 C126.2@6430,1303.5
NetC127_1: C127.1 J27.1 R43.1 S1.1 U6.2 | length 1281.5
  Top Layer w7: R43.1@4880.87,1308.9 U6.2@4975.83,1308.9
  Top Layer w8: R43.1@4880,1308.03 R43.1@4880.87,1308.9
  Top Layer w9: J27.1@4325,990 4325,1307.32
  Top Layer w10: S1.1@4075,1395 4075,1350 4117.68,1307.32 4325,1307.32 4879.29,1307.32 R43.1@4880,1308.03
NetC131_1: C131.1 R46.1 | length 83.5
  Bottom Layer w15: C131.1@1141.5,2083.5 C131.1@1150,2075
  Bottom Layer w25: C131.1@1141.5,2083.5 R46.1@1141.5,2155
NetC132_1: C132.1 D9.3 R32.1 | length 254.6
  Bottom Layer w15: C132.1@933,1579 931,1577 D9.3@931,1430.6 987.22,1430.6 R32.1@1022,1465.38
NetD1_1: D1.1 R34.1 | length 47
  Top Layer w10: R34.1@6870,3828.62 D1.1@6870,3875.65
NetD2_1: D2.1 R35.1 | length 48.4
  Top Layer w10: R35.1@6790,3827.24 D2.1@6790,3875.65
NetD4_1: D4.1 R49.1 | length 81.7
  Top Layer w12: D4.1@358.48,1050 362.58,1054.09 R49.1@362.58,1130
NetD5_2: D5.2 U8.2 | length 217.6
  MidLayer4 w20: v9(731,2915) 731,2844 v1(768.16,2806.84)
  Bottom Layer w10: v9(731,2915) 734.97,2911.03 U8.2@772.1,2911.03
  Bottom Layer w15: D5.2@768.16,2755.56 v1(768.16,2806.84)
NetD6_1: D6.1 R62.1 | length 58.8
  Top Layer w10: R62.1@375,2981.38 384.09,2972.28 D6.1@430,2972.28
NetD7_1: D7.1 R67.1 | length 71.7
  Top Layer w10: D7.1@465,3652.72 530.91,3652.72 R67.1@535,3648.62
NetD8_1: D8.1 R3.1 | length 50.4
  Top Layer w8: D8.1@5327.72,1120 5328.62,1120.91 R3.1@5328.62,1170
NetD10_1: D10.1 R66.1 | length 56.1
  Top Layer w10: R66.1@380,1895 382.72,1892.28 D10.1@435,1892.28
NetJ3_2: J3.2 J3.4 J3.6 J3.8 J3.10 J3.12 J3.14 J3.16 U1.14 | length 1017
  Top Layer w10: J3.16@5580,3637.05 5617.95,3637.05 v1(5620,3635)
  Top Layer w12: J3.2@5230,3637.05 J3.4@5280,3637.05 J3.6@5330,3637.05 J3.8@5380,3637.05 J3.10@5430,3637.05 J3.12@5480,3637.05 J3.14@5530,3637.05 J3.16@5580,3637.05
  MidLayer2-HiSp w7: v1(5620,3635) 5760,3635 5980,3855 v1(6100,3855)
  Bottom Layer w12: U1.14@6098.39,3796.61 U1.14@6098.39,3802.8 v1@6098.39,3851.61
NetJ5_2: J5.2 J5.4 J5.6 J5.8 R107.2 U1.17 | length 824.8
  Top Layer w10: J5.2@5562,4116.52 J5.4@5612,4116.52 J5.6@5662,4116.52 J5.8@5712,4116.52 5745.52,4116.52 v1(5747,4118)
  Top Layer w12: v1(6021.61,3751.61) R107.2@6021.61,3779.17
  MidLayer4 w10: v1(5747,4118) 5747,3893 5888.39,3751.61 v1(6021.61,3751.61)
  Bottom Layer w12: v1@6020,3750 v1(6021.61,3751.61) U1.17@6021.61,3802.8
NetJ6_1: J6.1 U6.18 | length 9493.9
  Top Layer w7: v1(5135,1030) v1@5139.21,1034.21
  Top Layer w8: v1@5139.21,1034.21 U6.18@5139.21,1125.83
  MidLayer4 w12: J6.1@140,5280 311,5109 311,4584 513.12,4381.88 513.12,4132.35 377.88,3997.12 377.88,1012.12 563,827 4932,827 v1(5135,1030)
NetJ6_2: J6.2 U6.19 | length 9482.5
  Top Layer w8: U6.19@5158.9,1125.83 5158.9,1011.1 v1(5160,1010)
  MidLayer4 w12: J6.2@140,5180 279,5041 279,4570.75 481.12,4368.63 481.12,4145.61 345.88,4010.37 345.88,998.86 549.75,795 4945.25,795 5160,1009.75 v1(5160,1010)
NetJ6_3: J6.3 U6.20 | length 9474.8
  Top Layer w8: U6.20@5178.58,1125.83 5178.58,1031.42 5185.25,1024.75 v1(5185.25,989.75)
  MidLayer4 w12: J6.3@140,5080 247,4973 247,4557.49 449.12,4355.37 449.12,4158.86 313.88,4023.63 313.88,985.61 536.49,763 4958.51,763 v1(5185.25,989.75)
NetJ6_4: J6.4 U6.21 | length 9488.1
  Top Layer w8: U6.21@5204.17,1151.42 5204.17,1130.83 5207.88,1127.12 v1(5207.88,967.12)
  MidLayer4 w12: J6.4@140,4980 215,4905 215,4544.24 417.12,4342.12 417.12,4172.12 281.88,4036.88 281.88,972.35 523.24,731 4971.76,731 v1(5207.88,967.12)
NetJ8_2: J8.2 J8.4 J8.6 J8.8 J8.10 J8.12 J8.14 J8.16 U2.13 | length 2441.1
  Top Layer w17: v1(3472.05,2472.05) U2.13@3472.05,2518.82
  Top Layer w20: v1(4750,2725) 5130,3105 5188.52,3163.52 J8.2@5230,3163.52 J8.4@5280,3163.52 J8.6@5330,3163.52 J8.8@5380,3163.52 J8.10@5430,3163.52 J8.12@5480,3163.52 J8.14@5530,3163.52 J8.16@5580,3163.52
  MidLayer4 w10: v1(3472.05,2472.05) 3515,2515 4540,2515 v1(4750,2725)
NetJ10_2: J10.2 J10.4 J10.6 J10.8 J10.10 J10.12 J10.14 J10.16 U2.11 | length 2343.5
  Top Layer w17: U2.11@3409.06,2518.82 3409.06,2470.94 v1(3410,2470)
  Top Layer w20: v1(5133.52,2688.52) J10.2@5230,2688.52 J10.4@5280,2688.52 J10.6@5330,2688.52 J10.8@5380,2688.52 J10.10@5430,2688.52 J10.12@5480,2688.52 J10.14@5530,2688.52 J10.16@5580,2688.52
  MidLayer4 w10: v1(3410,2470) 3450,2430 3570,2430 4873.52,2430 v1@5133.52,2690
NetJ13_1: J13.1 R91.2 | length 147.9
  Top Layer w9: R91.2@5935,673.62 J13.1@5935,821.48
NetJ13_3: J13.3 R90.2 | length 147.9
  Top Layer w9: R90.2@5985,673.62 J13.3@5985,821.48
NetJ13_5: J13.5 R106.2 | length 147.9
  Top Layer w9: R106.2@6035,673.62 J13.5@6035,821.48
NetJ13_7: J13.7 R105.2 | length 147.9
  Top Layer w9: R105.2@6085,673.62 J13.7@6085,821.48
NetJ16_3: J16.3 R97.2 R98.1 | length 151.5
  Top Layer w10: J16.3@1992,1245.48 v1(1992,1154) 1992,1125.62 R98.1@1993.62,1124
  Bottom Layer w10: v1(1992,1154) R97.2@2021.38,1154
NetJ16_5: J16.5 R99.2 R100.1 | length 229.8
  Top Layer w10: J16.5@2042,1245.48 2042,1077.38 R100.1@2038.62,1074 2093.62,1074 R99.2@2095,1075.38
NetJ17_2: J17.2 R26.2 | length 292.8
  Bottom Layer w10: J17.2@6270,170 6335,235 6335,360 6308.62,386.38 R26.2@6270,386.38
NetJ17_4: J17.4 R27.2 | length 277.5
  Bottom Layer w10: J17.4@6170,170 6220,220 6220,370 6205,385 6171.38,385 R27.2@6170,386.38
NetJ17_8: J17.8 U6.37 | length 2007.4
  Top Layer w7: U6.37@5060.47,1354.17 5060.47,1421.83 5133.64,1495 5335,1495 5603.74,1226.26 5603.74,891.26 5615,880 v1(5615,860)
  MidLayer2-HiSp w7: v1(5615,860) 5615,585 5820,380 5820,240 5840,220 5920,220 J17.8@5970,170
NetJ17_11: J17.11 R28.2 | length 116.4
  Bottom Layer w10: J17.11@5770,270 R28.2@5770,386.38
NetJ19_1: J19.1 R38.2 | length 151.2
  Top Layer w10: J19.1@6323,4328.98 6323,4180.62 R38.2@6325,4178.62
NetJ19_3: J19.3 R104.2 | length 151.2
  Top Layer w10: J19.3@6373,4328.98 6373,4180.62 R104.2@6375,4178.62
NetJ19_5: J19.5 R39.2 | length 151.2
  Top Layer w10: J19.5@6423,4328.98 6425,4326.98 R39.2@6425,4178.62
NetJ19_7: J19.7 R103.2 | length 147.6
  Top Layer w10: J19.7@6473,4328.98 6473,4184.24 R103.2@6475,4182.24
NetJ24_2: J24.2 R48.2 U7.8 | length 933.9
  MidLayer2-HiSp w12: J24.2@170,1105 448,1105 648,1305 v1(880,1305)
  Bottom Layer w12: v1(880,1305) 880.59,1305.59 U7.8@880.59,1366.46 U7.8@880.59,1378
  Bottom Layer w15: U7.8@880.59,1366.46 946.92,1366.46 R48.2@948,1365.38
NetL9_2: L9.2 L10.1 | length 162.1
  Top Layer w50: 6440,2675 6445,2680 L10.1@6445,2835
NetL10_2: L10.2 R30.1 R31.2 | length 257.4
  Top Layer w25: R30.1@6246.5,2860 6320,2860 L10.2@6345,2835 ; L10.2@6355,2860 6360,2865 6360,2905 6395,2940 R31.2@6447.01,2940
NetL11_1: L11.1 R37.1 | length 98.4
  Top Layer w9: L11.1@6245.16,3440 6253.66,3448.5 R37.1@6340,3448.5
NetL11_3: L11.3 R33.1 | length 99.8
  Top Layer w9: L11.3@6245.16,3640 R33.1@6345,3640
NetL14_2: L14.2 R58.1 R60.2 R61.2 | length 204.7
  Bottom Layer w9: R60.2@973.62,3110 1045,3110 1065,3090 v1(1170,3090)
  other v1: 1260,2785 1260,2830
NetL18_2: L18.2 L19.1 | length 130
  Top Layer w40: 6530,890 L19.1@6530,1020
NetL19_2: L19.2 R87.1 R88.2 | length 269.3
  Top Layer w30: R87.1@6331.5,1050 6430,1050 L19.2@6430,1020 6430,1130 R88.2@6451.75,1151.75
NetL20_1: L20.1 R95.1 | length 98.4
  Top Layer w9: L20.1@6225.16,1590 6233.66,1598.5 R95.1@6320,1598.5
NetL20_3: L20.3 R93.1 | length 98.4
  Top Layer w9: L20.3@6225.16,1790 6233.66,1781.5 R93.1@6320,1781.5
NetR3_2: R3.2 U6.22 | length 78.5
  Top Layer w7: U6.22@5204.17,1171.1 5204.78,1170.5 5280.88,1170.5 R3.2@5281.38,1170
  Top Layer w8: R3.2@5280.28,1171.1 R3.2@5280.88,1170.5
NetR7_1: R7.1 U1.6 | length 100.2
  Bottom Layer w12: R7.1@6055,4120 6055,4090 6072.8,4072.2 U1.6@6072.8,4027.2
NetR8_1: R8.1 U1.7 | length 93.5
  Bottom Layer w12: U1.7@6098.39,4027.2 6098.39,4118.39 R8.1@6100,4120
NetR9_1: R9.1 U2.12 | length 95.4
  Top Layer w12: R9.1@3440,2423.62 3440.55,2424.17 U2.12@3440.55,2518.82
NetR29_1: R29.1 R30.2 | length 75
  Top Layer w20: R29.1@6183.5,2785 R30.2@6183.5,2860
NetR45_1: R45.1 R46.2 U13.1 | length 179.8
  Top Layer w9: R45.1@1078.5,2225 R45.1@1080,2223.5
  Top Layer w20: v1(1080,2190) R45.1@1080,2223.5
  Bottom Layer w9: R46.2@1078.5,2155 R46.2@1080,2156.5
  Bottom Layer w15: U13.1@972.68,2148.39 1071.89,2148.39 R46.2@1078.5,2155
  Bottom Layer w20: R46.2@1080,2156.5 v1(1080,2190)
NetR47_1: R47.1 R51.2 TP13.1 | length 205.4
  Bottom Layer w12: TP13.1@605,1735 666.38,1673.62 R47.1@666.38,1610 R51.2@666.38,1555
NetR53_2: R53.2 U7.5 | length 92.5
  Bottom Layer w10: R53.2@713.62,1450 720,1443.62 720,1430 730.59,1419.41 U7.5@730.59,1364.49
NetR56_1: R56.1 U8.6 | length 96.2
  Bottom Layer w10: R56.1@710.53,3040.56 744.44,3040.56 772.1,3012.9 U8.6@772.1,2989.77
NetR60_1: R60.1 R63.2 U8.7 | length 122.2
  Bottom Layer w9: U8.7@921.71,2989.77 921.71,3058.09 R63.2@923.62,3060 923.62,3107.24 R60.1@926.38,3110
NetR67_2: R67.2 U14.4 | length 85
  Top Layer w9: R67.2@535,3595 U14.4@620,3595
NetR86_1: R86.1 R87.2 | length 70
  Top Layer w30: R86.1@6263.5,980 R87.2@6263.5,1050
NetR92_1: R92.1 R94.2 U10.8 | length 150.6
  Top Layer w7: U10.8@6248.9,1275.51 6248.9,1251.1 v4(6250,1250)
  Bottom Layer w8: R92.1@6265,1188.62 6273.62,1180 6305,1180 6310,1175 R94.2@6310,1168.62
  Bottom Layer w10: v4(6250,1250) 6265,1235 R92.1@6265,1188.62
OUT1_M: L2.4 R12.1 U2.48 | length 96.3
  Top Layer w20: R12.1@2835,3215 2895.59,3154.41 v2(2900,3154.41) v2@2895.59,3150
  other v2: 2930,3104.41 2990,3104.41 3050,3104.41 2960,3154.41 3020,3154.41 2055,3830 2105,3830 2055,3880 2105,3880 2055,3930 2105,3930
OUT1_P: L2.1 R11.1 U2.47 | length 75
  Top Layer w20: v2@2925,3275 R11.1@2925,3350
  other v2: 2940,3230 3000,3230 3060,3230 2910,3280 2970,3280 3030,3280 2215,3830 2265,3830 2215,3880 2265,3880 2215,3930 2265,3930
OUT2_M: L3.4 R14.1 U2.45 | length 72.1
  Top Layer w20: v2(3125,3350) 3130,3355 R14.1@3130,3420
  other v2: 3175,3200 3125,3230 3175,3260 3125,3290 3175,3320 2815,3830 2865,3830 2815,3880 2865,3880 2815,3930 2865,3930
OUT2_P: L3.1 R13.1 U2.44 | length 82.1
  Top Layer w20: v2(3285,3350) 3290,3355 R13.1@3290,3430
  other v2: 3235,3200 3285,3230 3235,3260 3285,3290 3235,3320 2975,3830 3025,3830 2975,3880 3025,3880 2975,3930 3025,3930
OUT3_M: L4.4 R16.1 U2.37 | length 82.1
  Top Layer w20: v2(3375,3350) 3380,3355 R16.1@3380,3430
  other v2: 3425,3200 3375,3230 3425,3260 3375,3290 3425,3320 3575,3830 3625,3830 3575,3880 3625,3880 3575,3930 3625,3930
OUT3_P: L4.1 R15.1 U2.36 | length 71.2
  Top Layer w20: v2(3537,3350) 3540,3353 R15.1@3540,3420
  other v2: 3487,3200 3537,3230 3487,3260 3537,3290 3487,3320 3735,3830 3785,3830 3735,3880 3785,3880 3735,3930 3785,3930
OUT4_M: L5.4 R18.1 U2.34 | length 70
  Top Layer w20: v2@3735,3270 R18.1@3735,3340
  other v2: 3600,3220 3660,3220 3720,3220 3630,3270 3690,3270 3750,3270 4335,3830 4385,3830 4335,3880 4385,3880 4335,3930 4385,3930
OUT4_P: L5.1 R17.1 U2.33 | length 96.9
  Top Layer w20: v2@3765,3150 v2(3760,3155) 3765,3155 R17.1@3825,3215
  other v2: 3610,3105 3670,3105 3730,3105 3640,3155 3700,3155 4495,3830 4545,3830 4495,3880 4545,3880 4495,3930 4545,3930
PCM_DEMP: R5.2 U1.10 U6.28 | length 7244
  Top Layer w7: U6.28@5204.17,1289.21 5204.46,1289.5 5249.5,1289.5 5260,1300 5395,1300 5505,1190 5505,900 5475,870 5475,835 5442.5,802.5 v1@5442.5,797.5
  Top Layer w12: R5.2@6175,3943.62 v1(6175,3975)
  MidLayer2-HiSp w10: v1(6545,445) 6545,1925 6590,1970 6590,2330 6570,2350 6570,3380 6740,3550 6840,3550 v1(6890,3600)
  MidLayer4 w10: v1(5440,800) 5440,210 5610,40 6325,40 6545,260 v1(6545,445) ; v1(6175,3975) 6215,3935 6715,3935 6905,3745 6905,3615 v1(6890,3600)
  Bottom Layer w12: v1(6175,3975) 6175.16,3975.16 U1.10@6175.16,4027.2
PCM_FLT: R4.2 U1.11 U6.26 | length 7058.8
  Top Layer w7: U6.26@5204.17,1249.84 5244.84,1249.84 v4(5245,1250) 5260,1250 5265,1245 5420,1245 5485,1180 5485,910 5445,870 v1(5445,840)
  Top Layer w12: v1(6175,3745) R4.2@6175,3776.38
  MidLayer2-HiSp w10: v1(6520,420) 6520,1950 6540,1970 6540,3385 6730,3575 6825,3575 v1(6850,3600)
  MidLayer4 w10: v1(5445,840) 5465,820 5465,230 5625,70 6310,70 6520,280 v1(6520,420) ; v1(6175,3745) 6320,3890 6725,3890 6865,3750 6865,3615 v1(6850,3600)
  Bottom Layer w12: v1(6175,3745) 6175.16,3745.16 U1.11@6175.16,3802.8
PCM_FMT: R6.2 U1.16 U6.40 | length 7403.3
  Top Layer w7: v1(4980,1355) 4980.83,1354.17 U6.40@5001.42,1354.17
  Top Layer w12: v1(6047.2,3735) 6060,3735 6072.8,3747.8 R6.2@6072.8,3779.17
  MidLayer2-HiSp w8: v1(6495,445) 6490,450 6490,3370 6720,3600 v1(6810,3600)
  MidLayer4 w8: v1(4980,1355) 4955,1355 4895,1295 4895,1125 4936,1084 5131,1084 5350,865 5455,865 5490,830 5490,255
  MidLayer4 w10: 5490,255 5645,100 6300,100 6495,295 v1(6495,445) ; v1(6047.2,3735) 6095,3735 6115,3715 6180,3715 6295,3830 6750,3830 6835,3745 6835,3625 v1(6810,3600)
  Bottom Layer w12: v1@6047.2,3732.2 v1(6047.2,3735) U1.16@6047.2,3802.8
PCM_MUTE_0: J5.1 J22.28 U3.21 | length 2357.1
  Top Layer w7: v1(5562,3893) J5.1@5562,3969.48 ; v4@5975,3100.79 U3.21@6016.14,3100.79 ; J22.28@6365,2223.52 v1(6365,2303.52)
  MidLayer4 w7: v4@5975,3101 5951,3101 5920,3070 5920,2445 6032,2333 6335.52,2333 v1(6365,2303.52)
  Bottom Layer w7: v1(5562,3893) 5930,3525 5930,3146 v4@5975,3101
  other v4: 5970,3101
PCM_MUTE_1: J5.3 J22.30 U3.22 | length 2342
  Top Layer w7: v1(5612,3893) J5.3@5612,3969.48 ; v4(5990,3081) 5990.1,3081.1 U3.22@6016.14,3081.1 ; J22.30@6415,2223.52 v1(6415,2303.52)
  MidLayer4 w7: v4(5990,3081) 5961,3081 5945,3065 5945,2470 6060,2355 6363.52,2355 v1(6415,2303.52)
  Bottom Layer w7: v1(5612,3893) 5945,3560 5945,3155.5 5995,3105.5 5995,3086 v4(5990,3081) v4@5991,3081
